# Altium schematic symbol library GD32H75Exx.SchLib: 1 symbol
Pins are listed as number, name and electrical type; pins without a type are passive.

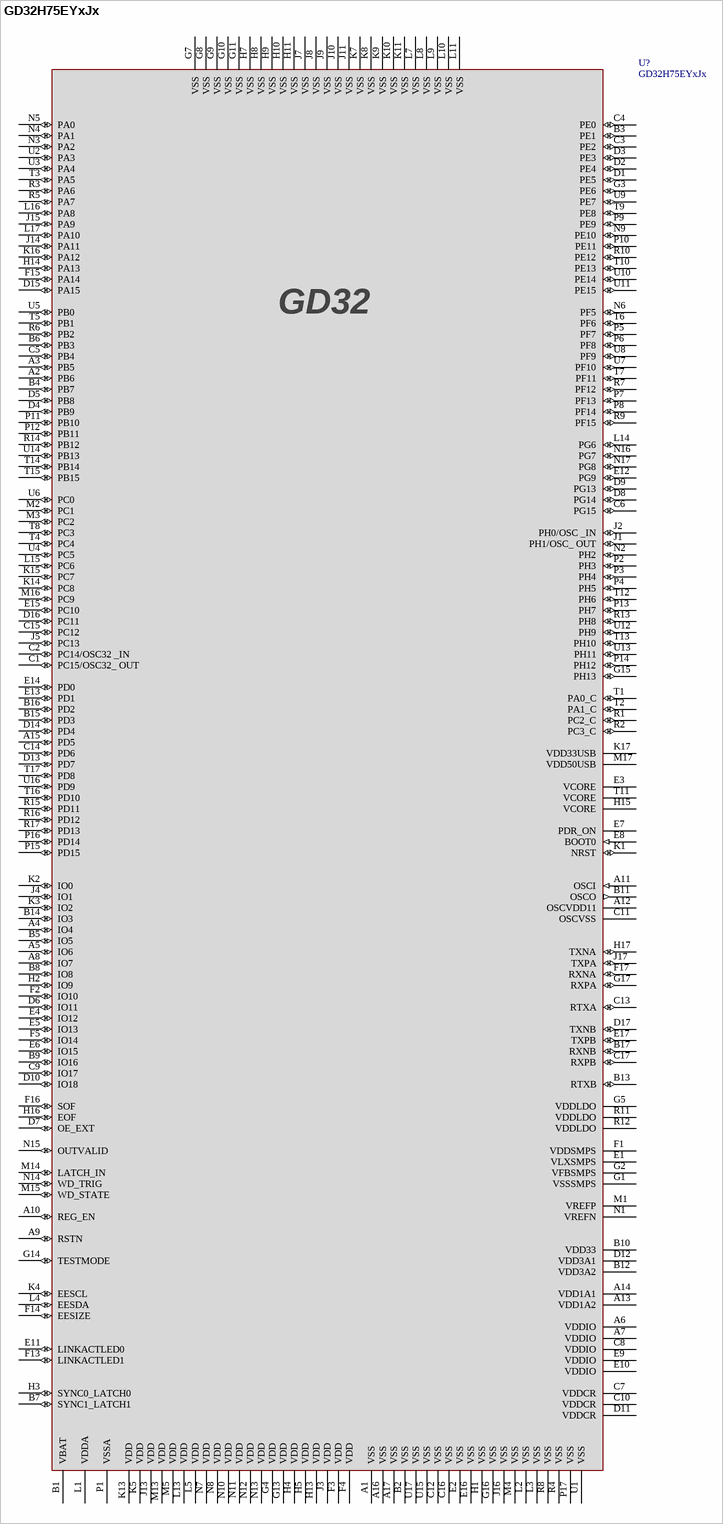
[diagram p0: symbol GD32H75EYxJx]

## GD32H75EYxJx
designator U?
footprint BGA240_14x14x1.07
pins: A1 VSS (power), A2 PB6 (io), A3 PB5 (io), A4 IO4 (io), A5 IO6 (io), A6 VDDIO (power), A7 VDDIO (power), A8 IO7 (io), A9 RSTN (io), A10 REG_EN (io), A11 OSCI (in), A12 OSCVDD11 (power), A13 VDD1A2 (power), A14 VDD1A1 (power), A15 PD5 (io), A16 VSS (power), A17 VSS (power), B1 VBAT (power), B2 VSS (power), B3 PE1 (io), B4 PB7 (io), B5 IO5 (io), B6 PB3 (io), B7 SYNC1_LATCH1 (io), B8 IO8 (io), B9 IO16 (io), B10 VDD33 (power), B11 OSCO (out), B12 VDD3A2 (power), B13 RTXB (io), B14 IO3 (io), B15 PD3 (io), B16 PD2 (io), B17 RXNB (io), C1 PC15/OSC32_ OUT (io), C2 PC14/OSC32 _IN (io), C3 PE2 (io), C4 PE0 (io), C5 PB4 (io), C6 PG15 (io), C7 VDDCR (power), C8 VDDIO (power), C9 IO17 (io), C10 VDDCR (power), C11 OSCVSS (power), C12 VSS (power), C13 RTXA (io), C14 PD6 (io), C15 PC12 (io), C16 VSS (power), C17 RXPB (io), D1 PE5 (io), D2 PE4 (io), D3 PE3 (io), D4 PB9 (io), D5 PB8 (io), D6 IO11 (io), D7 OE_EXT (io), D8 PG14 (io), D9 PG13 (io), D10 IO18 (io), D11 VDDCR (power), D12 VDD3A1 (power), D13 PD7 (io), D14 PD4 (io), D15 PA15 (io), D16 PC11 (io), D17 TXNB (io), E1 VLXSMPS (power), E2 VSS (power), E3 VCORE (power), E4 IO12 (io), E5 IO13 (io), E6 IO15 (io), E7 PDR_ON (power), E8 BOOT0 (in), E9 VDDIO (power), E10 VDDIO (power), E11 LINKACTLED0 (io), E12 PG9 (io), E13 PD1 (io), E14 PD0 (io), E15 PC10 (io), E16 VSS (power), E17 TXPB (io), F1 VDDSMPS (power), F2 IO10 (io), F3 VDD (power), F4 VDD (power), F5 IO14 (io), F13 LINKACTLED1 (io), F14 EESIZE (io), F15 PA14 (io), F16 SOF (io), F17 RXNA (io), G1 VSSSMPS (power), G2 VFBSMPS (power), G3 PE6 (io), G4 VDD (power), G5 VDDLDO (power), G7 VSS (power), G8 VSS (power), G9 VSS (power), G10 VSS (power), G11 VSS (power), G13 VDD (power), G14 TESTMODE (io), G15 PH13 (io), G16 VSS (power), G17 RXPA (io), H1 VSS (power), H2 IO9 (io), H3 SYNC0_LATCH0 (io), H4 VDD (power), H5 VDD (power), H7 VSS (power), H8 VSS (power), H9 VSS (power), H10 VSS (power), H11 VSS (power), H13 VDD (power), H14 PA13 (io), H15 VCORE (power), H16 EOF (io), H17 TXNA (io), J1 PH1/OSC_ OUT (io), J2 PH0/OSC _IN (io), J3 VDD (power), J4 IO1 (io), J5 PC13 (io), J7 VSS (power), J8 VSS (power), J9 VSS (power), J10 VSS (power), J11 VSS (power), J13 VDD (power), J14 PA11 (io), J15 PA9 (io), J16 VSS (power), J17 TXPA (io), K1 NRST (io), K2 IO0 (io), K3 IO2 (io), K4 EESCL (io), K5 VDD (power), K7 VSS (power), K8 VSS (power), K9 VSS (power), K10 VSS (power), K11 VSS (power), K13 VDD (power), K14 PC8 (io), K15 PC7 (io), K16 PA12 (io), K17 VDD33USB (power), L1 VDDA (power), L2 VSS (power), L3 VSS (power), L4 EESDA (io), L5 VDD (power), L7 VSS (power), L8 VSS (power), L9 VSS (power), L10 VSS (power), L11 VSS (power), L13 VDD (power), L14 PG6 (io), L15 PC6 (io), L16 PA8 (io), L17 PA10 (io), M1 VREFP (power), M2 PC1 (io), M3 PC2 (io), M4 VSS (power), M5 VDD (power), M13 VDD (power), M14 LATCH_IN (io), M15 WD_STATE (io), M16 PC9 (io), M17 VDD50USB (power), N1 VREFN (power), N2 PH2 (io), N3 PA2 (io), N4 PA1 (io), N5 PA0 (io), N6 PF5 (io), N7 VDD (power), N8 VDD (power), N9 PE10 (io), N10 VDD (power), N11 VDD (power), N12 VDD (power), N13 VDD (power), N14 WD_TRIG (io), N15 OUTVALID (io), N16 PG7 (io), N17 PG8 (io), P1 VSSA (power), P2 PH3 (io), P3 PH4 (io), P4 PH5 (io), P5 PF7 (io), P6 PF8 (io), P7 PF13 (io), P8 PF14 (io), P9 PE9 (io), P10 PE11 (io), P11 PB10 (io), P12 PB11 (io), P13 PH7 (io), P14 PH12 (io), P15 PD15 (io), P16 PD14 (io), P17 VSS (power), R1 PC2_C (io), R2 PC3_C (io), R3 PA6 (io), R4 VSS (power), R5 PA7 (io), R6 PB2 (io), R7 PF12 (io), R8 VSS (power), R9 PF15 (io), R10 PE12 (io), R11 VDDLDO (power), R12 VDDLDO (power), R13 PH8 (io), R14 PB12 (io), R15 PD11 (io), R16 PD12 (io), R17 PD13 (io), T1 PA0_C (io), T2 PA1_C (io), T3 PA5 (io), T4 PC4 (io), T5 PB1 (io), T6 PF6 (io), T7 PF11 (io), T8 PC3 (io), T9 PE8 (io), T10 PE13 (io), T11 VCORE (power), T12 PH6 (io), T13 PH10 (io), T14 PB14 (io), T15 PB15 (io), T16 PD10 (io), T17 PD8 (io), U1 VSS (power), U2 PA3 (io), U3 PA4 (io), U4 PC5 (io), U5 PB0 (io), U6 PC0 (io), U7 PF10 (io), U8 PF9 (io), U9 PE7 (io), U10 PE14 (io), U11 PE15 (io), U12 PH9 (io), U13 PH11 (io), U14 PB13 (io), U15 VSS (power), U16 PD9 (io), U17 VSS (power)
